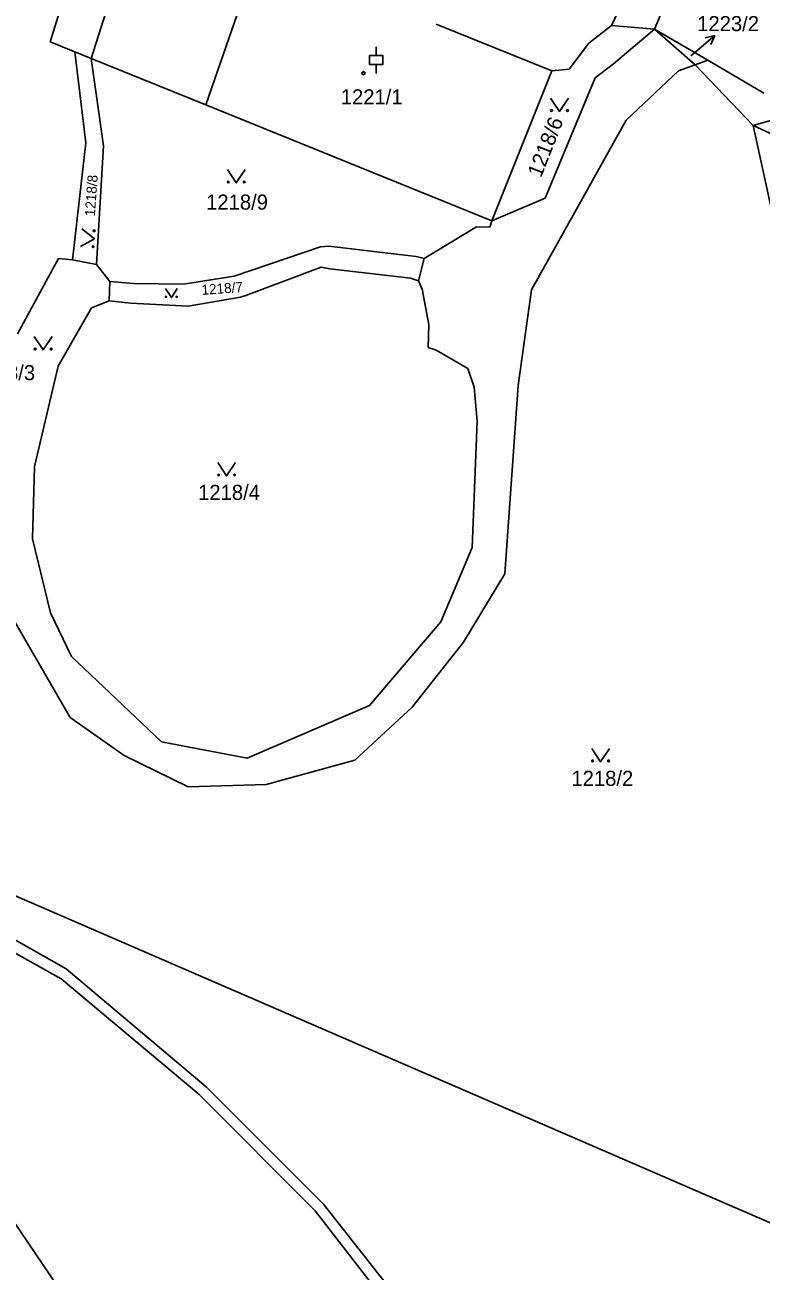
# Model space of a CAD drawing. Extents: x -593183 to -588034, y -1130415 to -1124994.
# Drawn here: x -590785.7 to -590703, y -1129329.8 to -1129189.7 of the extents above; entities that cross this region are included whole.
import ezdxf

# ---------------------------------------------------------------- set-up
doc = ezdxf.new("R2010")
doc.units = 0
for name, color, linetype in [('Vrstva 1', 7, 'Continuous'), ('Vrstva 16', 7, 'Continuous'), ('Vrstva 18', 7, 'Continuous'), ('Vrstva 19', 7, 'Continuous'), ('Vrstva 25', 7, 'Continuous')]:
    doc.layers.add(name, color=color, linetype=linetype)

msp = doc.modelspace()

# ---------------------------------------------------------------- linework, layer by layer
at = {"layer": 'Vrstva 1'}
for p, q in [((-590714.96, -1129190.19), (-590694.63, -1129141.99)), ((-590768.2, -1129144.82), (-590782.9, -1129191.62)), ((-590769.68, -1129166.43), (-590778.27, -1129193.47)), ((-590755.98, -1129171.48), (-590765.41, -1129198.68)), ((-590715.73, -1129181.28), (-590719.8, -1129189.78)), ((-590739.49, -1129189.64), (-590726.5, -1129194.86)), ((-590719.8, -1129189.78), (-590722.34, -1129191.75)), ((-590719.8, -1129189.78), (-590714.96, -1129190.19)), ((-590714.96, -1129190.19), (-590719.55, -1129194.08)), ((-590714.96, -1129190.19), (-590708.97, -1129193.69)), ((-590714.96, -1129190.19), (-590710.38, -1129194.2)), ((-590782.9, -1129191.62), (-590780.11, -1129192.74)), ((-590722.34, -1129191.75), (-590724.56, -1129194.68)), ((-590780.11, -1129192.74), (-590778.88, -1129202.95)), ((-590780.11, -1129192.74), (-590778.27, -1129193.47)), ((-590778.27, -1129193.47), (-590776.91, -1129203.32)), ((-590778.27, -1129193.47), (-590765.41, -1129198.68)), ((-590724.56, -1129194.68), (-590726.5, -1129194.86)), ((-590719.55, -1129194.08), (-590721.62, -1129195.67)), ((-590712.26, -1129194.87), (-590710.38, -1129194.2)), ((-590708.97, -1129193.69), (-590710.38, -1129194.2)), ((-590710.38, -1129194.2), (-590703.84, -1129201.02)), ((-590708.97, -1129193.69), (-590702.65, -1129197.37)), ((-590726.5, -1129194.86), (-590733.24, -1129211.72)), ((-590721.62, -1129195.67), (-590727.25, -1129209.18)), ((-590718.15, -1129200.41), (-590712.26, -1129194.87)), ((-590765.41, -1129198.68), (-590733.24, -1129211.72)), ((-590728.77, -1129219.49), (-590718.15, -1129200.41)), ((-590703.84, -1129201.02), (-590694.66, -1129205.29)), ((-590703.84, -1129201.02), (-590683.68, -1129294.09)), ((-590778.88, -1129202.95), (-590780.38, -1129216.11)), ((-590777.67, -1129216.64), (-590776.91, -1129203.32)), ((-590727.25, -1129209.18), (-590733.24, -1129211.72)), ((-590734.98, -1129212.41), (-590740.86, -1129215.97)), ((-590733.45, -1129212.45), (-590734.98, -1129212.41)), ((-590733.24, -1129211.72), (-590733.45, -1129212.45)), ((-590752.51, -1129214.65), (-590762.22, -1129217.96)), ((-590751.57, -1129214.58), (-590752.51, -1129214.65)), ((-590741.76, -1129215.75), (-590751.57, -1129214.58)), ((-590740.86, -1129215.97), (-590741.76, -1129215.75)), ((-590786.57, -1129224.46), (-590781.95, -1129215.96)), ((-590780.38, -1129216.11), (-590781.95, -1129215.96)), ((-590777.67, -1129216.64), (-590780.38, -1129216.11)), ((-590776.18, -1129218.55), (-590777.67, -1129216.64)), ((-590752.43, -1129216.93), (-590760.9, -1129220.13)), ((-590751.46, -1129217.12), (-590752.43, -1129216.93)), ((-590742.38, -1129218.18), (-590751.46, -1129217.12)), ((-590740.86, -1129215.97), (-590741.49, -1129218.48)), ((-590776.18, -1129218.55), (-590776.25, -1129220.75)), ((-590773.53, -1129218.77), (-590776.18, -1129218.55)), ((-590762.22, -1129217.96), (-590767.89, -1129218.87)), ((-590741.49, -1129218.48), (-590742.38, -1129218.18)), ((-590741.08, -1129219.43), (-590741.49, -1129218.48)), ((-590767.89, -1129218.87), (-590773.53, -1129218.77)), ((-590740.33, -1129223.38), (-590741.08, -1129219.43)), ((-590730.26, -1129230.24), (-590728.77, -1129219.49)), ((-590776.25, -1129220.75), (-590778.24, -1129221.51)), ((-590773.84, -1129221.01), (-590776.25, -1129220.75)), ((-590767.36, -1129221.34), (-590773.84, -1129221.01)), ((-590761.49, -1129220.31), (-590767.36, -1129221.34)), ((-590760.9, -1129220.13), (-590761.49, -1129220.31)), ((-590778.24, -1129221.51), (-590782, -1129228.07)), ((-590740.41, -1129225.98), (-590740.33, -1129223.38)), ((-590739.48, -1129226.27), (-590740.41, -1129225.98)), ((-590735.94, -1129228.33), (-590739.48, -1129226.27)), ((-590782, -1129228.07), (-590784.64, -1129239.37)), ((-590735.21, -1129230.45), (-590735.94, -1129228.33)), ((-590734.89, -1129234.26), (-590735.21, -1129230.45)), ((-590731.76, -1129251.44), (-590730.26, -1129230.24)), ((-590735.46, -1129248.48), (-590734.89, -1129234.26)), ((-590784.64, -1129239.37), (-590784.89, -1129247.5)), ((-590784.89, -1129247.5), (-590782.87, -1129255.83)), ((-590738.96, -1129256.84), (-590735.46, -1129248.48)), ((-590736.41, -1129259.13), (-590731.76, -1129251.44)), ((-590782.87, -1129255.83), (-590780.5, -1129260.71)), ((-590786.88, -1129256.83), (-590780.64, -1129267.57)), ((-590746.99, -1129266.24), (-590738.96, -1129256.84)), ((-590742.18, -1129266.43), (-590736.41, -1129259.13)), ((-590780.5, -1129260.71), (-590770.36, -1129270.32)), ((-590760.74, -1129272.15), (-590746.99, -1129266.24)), ((-590780.64, -1129267.57), (-590774.57, -1129271.84)), ((-590748.65, -1129272.39), (-590742.18, -1129266.43)), ((-590770.36, -1129270.32), (-590760.74, -1129272.15)), ((-590774.57, -1129271.84), (-590767.38, -1129275.38)), ((-590758.61, -1129275.1), (-590748.65, -1129272.39)), ((-590767.38, -1129275.38), (-590758.61, -1129275.1)), ((-590809.93, -1129277.63), (-590692.63, -1129328.44)), ((-590781.1, -1129295.84), (-590805.44, -1129282.09)), ((-590806.42, -1129283.19), (-590781.64, -1129296.97)), ((-590781.64, -1129296.97), (-590766.19, -1129309.94)), ((-590765.35, -1129309.11), (-590781.1, -1129295.84)), ((-590752.18, -1129322.31), (-590765.35, -1129309.11)), ((-590766.19, -1129309.94), (-590753.1, -1129323.06)), ((-590780.84, -1129333.35), (-590791.21, -1129318.04)), ((-590740.67, -1129336.89), (-590752.18, -1129322.31)), ((-590753.1, -1129323.06), (-590741.86, -1129337.57))]:
    msp.add_line(p, q, dxfattribs=at)
msp.add_lwpolyline([(-590703.84, -1129201.02), (-590699.19, -1129199.67), (-590695.61, -1129199.17), (-590694.85, -1129199.21)], dxfattribs=at)
at = {"layer": 'Vrstva 16'}
msp.add_line((-590710.88, -1129193.17), (-590710.47, -1129192.83), dxfattribs=at)
at = {"layer": 'Vrstva 25'}
for p, q in [((-590710.47, -1129192.83), (-590708.17, -1129190.91)), ((-590746.24, -1129193.16), (-590746.24, -1129192.16)), ((-590746.24, -1129194.16), (-590746.24, -1129195.16))]:
    msp.add_line(p, q, dxfattribs=at)
for points in [[(-590709.25, -1129191.17), (-590708.17, -1129190.91), (-590708.61, -1129191.93)], [(-590724.63, -1129197.93), (-590725.63, -1129199.43), (-590726.63, -1129197.93)], [(-590760.97, -1129205.97), (-590761.97, -1129207.47), (-590762.97, -1129205.97)], [(-590779.33, -1129212.65), (-590777.91, -1129213.75), (-590779.48, -1129214.64)], [(-590768.6, -1129219.35), (-590769.27, -1129220.36), (-590769.94, -1129219.35)], [(-590782.68, -1129224.76), (-590783.68, -1129226.26), (-590784.68, -1129224.76)], [(-590762.05, -1129238.92), (-590763.05, -1129240.42), (-590764.05, -1129238.92)], [(-590720.01, -1129271.07), (-590721.01, -1129272.57), (-590722.01, -1129271.07)]]:
    msp.add_lwpolyline(points, dxfattribs=at)
msp.add_lwpolyline([(-590746.99, -1129194.16), (-590745.49, -1129194.16), (-590745.49, -1129193.16), (-590746.99, -1129193.16)], close=True, dxfattribs=at)
for centre, radius in [((-590747.67, -1129195.14), 0.175), ((-590747.67, -1129195.14), 0.15), ((-590726.53, -1129199.33), 0.1), ((-590724.73, -1129199.33), 0.1), ((-590762.87, -1129207.37), 0.1), ((-590761.07, -1129207.37), 0.1), ((-590777.95, -1129212.85), 0.1), ((-590778.07, -1129214.64), 0.1), ((-590769.87, -1129220.29), 0.067), ((-590768.67, -1129220.29), 0.067), ((-590784.58, -1129226.16), 0.1), ((-590782.78, -1129226.16), 0.1), ((-590763.95, -1129240.32), 0.1), ((-590762.15, -1129240.32), 0.1), ((-590721.91, -1129272.47), 0.1), ((-590720.11, -1129272.47), 0.1)]:
    msp.add_circle(centre, radius, dxfattribs=at)

# ---------------------------------------------------------------- texts
at = {"layer": 'Vrstva 16'}
msp.add_text('1223/2', height=1.7, dxfattribs=at).set_placement((-590710.15, -1129190.41))
at = {"layer": 'Vrstva 18'}
for s, height, p in [('1223/2', 0.01, (-590710.88, -1129193.17)), ('1218/9', 1.7, (-590765.36, -1129210.48)), ('1218/3', 1.7, (-590791.54, -1129229.66)), ('1218/4', 1.7, (-590766.26, -1129243.12)), ('1218/2', 1.7, (-590724.29, -1129275.27))]:
    msp.add_text(s, height=height, dxfattribs=at).set_placement(p)
for s, height, rotation, p in [('1218/6', 1.7, 68.4986, (-590727.71, -1129206.96)), ('1218/8', 1.14, 85.9053, (-590777.87, -1129211.26)), ('1218/7', 1.14, 4.0856, (-590765.84, -1129220.07))]:
    msp.add_text(s, height=height, rotation=rotation, dxfattribs=at).set_placement(p)
at = {"layer": 'Vrstva 19'}
msp.add_text('1221/1', height=1.7, dxfattribs=at).set_placement((-590750.22, -1129198.65))

doc.saveas('drawing.dxf')
